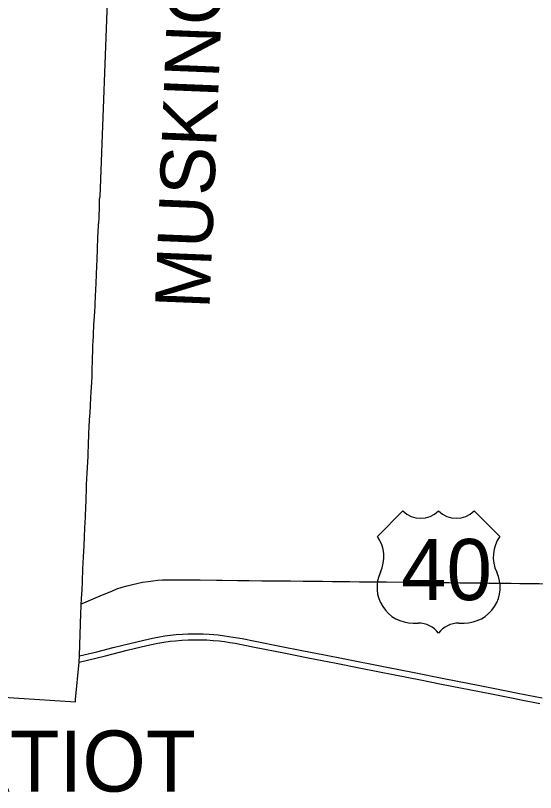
# Model space of a CAD drawing. Extents: x 2015843 to 2287843, y 623733 to 799733.
# Drawn here: x 2066735 to 2076267, y 703656 to 717899 of the extents above; entities that cross this region are included whole.
import ezdxf

# ---------------------------------------------------------------- set-up
doc = ezdxf.new("R2010")
doc.units = 0
for name, color, linetype in [('GM_X_Corporation_Text', 7, 'Continuous'), ('GM_X_County', 7, 'Continuous'), ('GM_X_County_Text', 7, 'Continuous'), ('GM_X_US_Location', 7, 'Continuous'), ('GM_X_US_Route', 7, 'Continuous'), ('GM_X_US_Shield', 7, 'Continuous'), ('UT_P_Electric', 7, 'Continuous')]:
    doc.layers.add(name, color=color, linetype=linetype)

msp = doc.modelspace()

# ---------------------------------------------------------------- linework, layer by layer
at = {"layer": 'GM_X_County'}
msp.add_lwpolyline([(2065569, 705466), (2067835, 705316), (2067837, 705359), (2067900, 706047), (2067905, 706164), (2067931, 706936), (2067936, 707072), (2067940, 707117), (2067946, 707183), (2067947, 707215), (2067954, 707359), (2067961, 707524), (2067970, 707757), (2067981, 707974), (2067991, 708179), (2068005, 708510), (2068016, 708705), (2068023, 708906), (2068028, 708984), (2068031, 709079), (2068034, 709180), (2068039, 709298), (2068045, 709411), (2068049, 709507), (2068064, 709819), (2068067, 709901), (2068070, 709999), (2068075, 710096), (2068077, 710162), (2068078, 710191), (2068081, 710243), (2068088, 710360), (2068094, 710487), (2068102, 710620), (2068110, 710750), (2068118, 710896), (2068124, 710996), (2068133, 711176), (2068137, 711274), (2068140, 711348), (2068141, 711427), (2068144, 711549), (2068146, 711634), (2068150, 711735), (2068154, 711832), (2068158, 711944), (2068162, 712010), (2068164, 712093), (2068168, 712179), (2068173, 712237), (2068176, 712302), (2068188, 712466), (2068196, 712580), (2068204, 712783), (2068206, 712844), (2068209, 712908), (2068211, 712958), (2068214, 713039), (2068217, 713105), (2068221, 713203), (2068223, 713260), (2068226, 713317), (2068229, 713415), (2068238, 713627), (2068246, 713823), (2068259, 714051), (2068264, 714116), (2068267, 714165), (2068269, 714214), (2068274, 714382), (2068274, 714452), (2068274, 714489), (2068277, 714538), (2068279, 714553), (2068282, 714565), (2068284, 714574), (2068438, 718640)], dxfattribs=at)
at = {"layer": 'GM_X_US_Route'}
for points in [[(2067941, 707114), (2067989, 707134), (2068330, 707278), (2068500, 707349), (2068595, 707386), (2068693, 707420), (2068782, 707446), (2068878, 707471), (2068957, 707488), (2069060, 707508), (2069164, 707525), (2069254, 707538), (2069344, 707545), (2069432, 707551), (2069582, 707555), (2069931, 707552), (2070123, 707551), (2070418, 707547), (2070526, 707545), (2070806, 707542), (2071019, 707540), (2071249, 707538), (2071437, 707536), (2071624, 707534), (2071775, 707533), (2072006, 707530), (2072365, 707527), (2072544, 707526), (2072861, 707523), (2073042, 707520), (2073204, 707517), (2073313, 707516), (2073534, 707515), (2074207, 707508), (2074437, 707506), (2074683, 707503), (2074881, 707500), (2075371, 707496), (2075409, 707495), (2075729, 707490), (2075740, 707490), (2075824, 707490)], [(2075824, 707490), (2075980, 707489), (2076143, 707488), (2076333, 707485), (2076689, 707473), (2076964, 707462), (2077183, 707450), (2077569, 707427), (2077877, 707404), (2078140, 707385), (2078362, 707371), (2078548, 707357), (2078559, 707356)]]:
    msp.add_lwpolyline(points, dxfattribs=at)
at = {"layer": 'GM_X_US_Shield'}
for p, q in [((2073837, 708817), (2073370, 708350)), ((2075611, 708350), (2075144, 708817)), ((2074024, 706762), (2074117, 706762)), ((2074864, 706762), (2074957, 706762))]:
    msp.add_line(p, q, dxfattribs=at)
for centre, radius, start, end in [((2074164, 709150), 467, 225.573, 314.427), ((2074817, 709150), 467, 225.573, 314.427), ((2072834, 707975), 654, 334.5471, 35.0009), ((2076147, 707975), 654, 144.9991, 205.4529), ((2074016, 707416), 654, 154.8319, 270.6383), ((2074965, 707416), 654, 269.3617, 25.1681), ((2074117, 706295), 467, 36.8699, 90), ((2074864, 706295), 467, 90, 143.1301)]:
    msp.add_arc(centre, radius, start, end, dxfattribs=at)
at = {"layer": 'UT_P_Electric'}
for points in [[(2067906, 706161), (2068226, 706236), (2068528, 706312), (2068830, 706388), (2069085, 706449), (2069246, 706484), (2069374, 706509), (2069471, 706525), (2069569, 706538), (2069683, 706550), (2069797, 706558), (2069895, 706562), (2070042, 706565), (2070173, 706563), (2070288, 706559), (2070370, 706553), (2070451, 706545), (2070565, 706530), (2070727, 706504), (2070888, 706476), (2071130, 706431), (2071612, 706334), (2071982, 706261), (2072400, 706178), (2072770, 706105), (2073510, 705958), (2074041, 705854), (2074588, 705745), (2075248, 705615), (2075489, 705566), (2075795, 705506), (2075884, 705488), (2076133, 705439), (2076390, 705389)], [(2067901, 706044), (2068386, 706162), (2068784, 706262), (2069038, 706325), (2069198, 706361), (2069343, 706391), (2069456, 706411), (2069570, 706427), (2069668, 706438), (2069782, 706447), (2069897, 706453), (2070012, 706456), (2070127, 706455), (2070242, 706451), (2070356, 706444), (2070471, 706433), (2070569, 706422), (2070666, 706407), (2070763, 706390), (2071085, 706328), (2071713, 706203), (2072098, 706126), (2072613, 706025), (2073064, 705935), (2073691, 705811), (2074157, 705718), (2074543, 705641), (2075428, 705467), (2075888, 705376), (2075913, 705371), (2075975, 705359), (2076346, 705286)]]:
    msp.add_lwpolyline(points, dxfattribs=at)

# ---------------------------------------------------------------- texts
at = {"layer": 'GM_X_Corporation_Text'}
msp.add_text('GRATIOT', height=1120, rotation=0, dxfattribs=at).set_placement((2063383, 703671))
at = {"layer": 'GM_X_County_Text'}
msp.add_text('MUSKINGUM COUNTY', height=1000, rotation=87.6671, dxfattribs=at).set_placement((2070290, 712509))
at = {"layer": 'GM_X_US_Location'}
for s in ['0', '/']:
    msp.add_text(s, height=1, dxfattribs=at).set_placement((2074615, 707718))
msp.add_text('40', height=1, rotation=0, dxfattribs=at).set_placement((2074409, 707511))
at = {"layer": 'GM_X_US_Shield'}
msp.add_text('40', height=1120.7, dxfattribs=at).set_placement((2073803, 707182))

doc.saveas('drawing.dxf')
